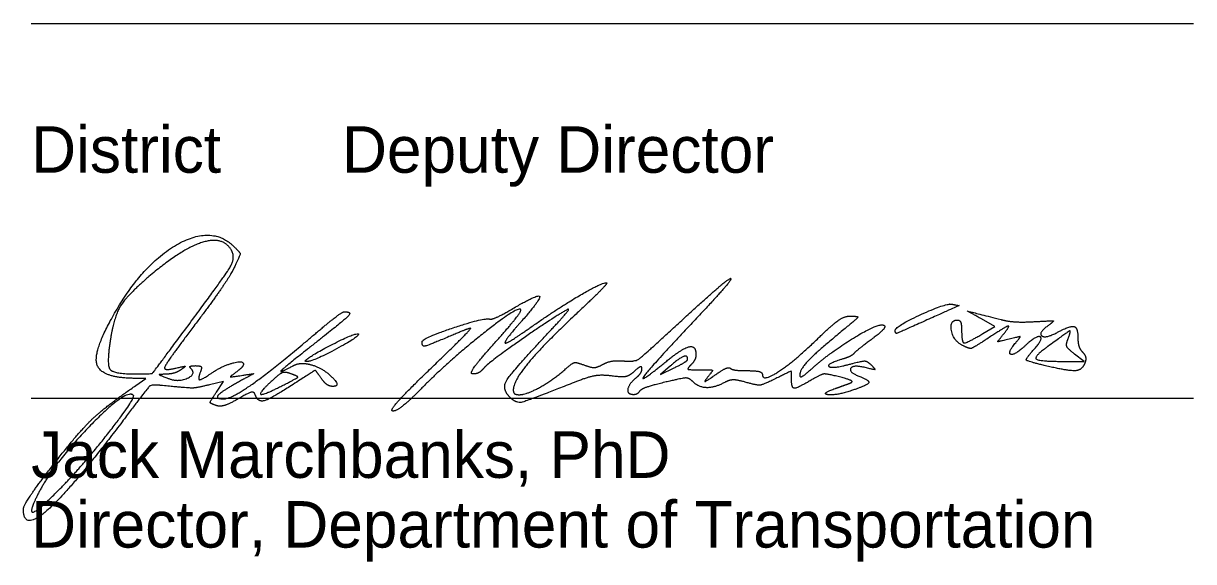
# Model space of a CAD drawing. Extents: x 0 to 81.5, y 0 to 35.2.
# Drawn here: x 77.956 to 81.479, y 33.533 to 35.155 of the extents above; entities that cross this region are included whole.
import ezdxf

# ---------------------------------------------------------------- set-up
doc = ezdxf.new("R2010")
doc.units = 0
doc.layers.add('SH_Data', color=7, linetype='Continuous')
doc.layers.add('SH_Text', color=7, linetype='Continuous')

msp = doc.modelspace()

# ---------------------------------------------------------------- linework, layer by layer
at = {"layer": 'SH_Data'}
for p, q in [((77.9791, 35.1551), (81.4791, 35.1551)), ((77.9791, 34.0257), (81.4791, 34.0257))]:
    msp.add_line(p, q, dxfattribs=at)
at = {"layer": 'SH_Text'}
for p, q in [((78.4414, 34.2307), (78.4414, 34.2307)), ((80.5807, 34.2298), (80.5807, 34.2298)), ((79.9557, 34.1428), (79.9557, 34.1428)), ((78.8067, 34.1408), (78.8067, 34.1408)), ((79.1786, 34.1118), (79.1786, 34.1118)), ((81.0332, 34.1236), (81.0332, 34.1236)), ((78.7619, 34.0992), (78.7619, 34.0992))]:
    msp.add_line(p, q, dxfattribs=at)
for points in [[(80.8445, 34.2203), (80.8809, 34.2418), (80.8402, 34.2647)], [(81.0932, 34.1367), (81.1494, 34.1368), (81.1207, 34.1589)], [(79.904, 34.1232), (79.8744, 34.0975), (79.9151, 34.1172)], [(78.2938, 34.0637), (78.3244, 34.085), (78.2866, 34.0856)], [(78.5367, 34.0439), (78.5579, 34.0762), (78.5162, 34.0662)]]:
    msp.add_lwpolyline(points, dxfattribs=at)
for points in [[(78.2301, 34.2815), (78.3163, 34.4318), (78.5245, 34.5479), (78.5901, 34.4822)], [(78.5812, 34.473), (78.5552, 34.515), (78.4291, 34.4739), (78.3338, 34.3922)], [(78.4414, 34.2307), (78.5628, 34.3941), (78.5952, 34.4503), (78.5812, 34.473)], [(78.5901, 34.4822), (78.6089, 34.4634), (78.6089, 34.4584), (78.5906, 34.42)], [(78.3338, 34.3922), (78.2671, 34.3352), (78.2283, 34.2711), (78.2172, 34.1998)], [(78.5906, 34.42), (78.5797, 34.397), (78.5279, 34.3214), (78.4757, 34.252)], [(79.4838, 34.2399), (79.5644, 34.2965), (79.6957, 34.3738), (79.7114, 34.3738)], [(79.7114, 34.3738), (79.7163, 34.3738), (79.675, 34.3312), (79.6196, 34.2791)], [(79.9381, 34.2603), (80.0131, 34.3294), (80.0791, 34.386), (80.0849, 34.3861)], [(80.0849, 34.3861), (80.0906, 34.3862), (80.0386, 34.326), (79.9692, 34.2524)], [(79.4249, 34.2934), (79.5036, 34.3396), (79.5159, 34.3263), (79.4566, 34.259)], [(78.8202, 34.208), (78.8707, 34.2508), (78.9162, 34.286), (78.9213, 34.2861)], [(78.9213, 34.2861), (78.9462, 34.2866), (78.9228, 34.261), (78.8369, 34.1938)], [(79.4529, 34.2932), (79.4433, 34.3028), (79.2336, 34.1359), (79.1557, 34.0566)], [(79.5932, 34.2927), (79.5442, 34.265), (79.3558, 34.1327), (79.3426, 34.1168)], [(79.3592, 34.2642), (79.3648, 34.2624), (79.3943, 34.2755), (79.4249, 34.2934)], [(79.3751, 34.1928), (79.4214, 34.2445), (79.4564, 34.2897), (79.4529, 34.2932)], [(79.528, 34.2138), (79.5742, 34.2631), (79.6035, 34.2986), (79.5932, 34.2927)], [(80.5807, 34.2298), (80.5807, 34.2422), (80.7335, 34.3126), (80.7524, 34.3089)], [(80.7524, 34.3089), (80.7731, 34.3048), (80.7739, 34.3053), (80.6522, 34.2506)], [(80.8402, 34.2647), (80.7973, 34.2888), (80.7964, 34.2889), (80.8994, 34.2625)], [(78.2866, 34.0856), (78.1887, 34.0873), (78.1653, 34.1684), (78.2301, 34.2815)], [(78.4757, 34.252), (78.4234, 34.1827), (78.3807, 34.122), (78.3807, 34.1172)], [(79.1559, 34.1956), (79.1561, 34.2062), (79.3435, 34.2694), (79.3592, 34.2642)], [(79.4566, 34.259), (79.4286, 34.2272), (79.4057, 34.1975), (79.4057, 34.1931)], [(79.6196, 34.2791), (79.52, 34.1853), (79.4307, 34.0772), (79.4307, 34.0502)], [(79.7631, 34.138), (79.7966, 34.1351), (79.8201, 34.1516), (79.9381, 34.2603)], [(79.9692, 34.2524), (79.8397, 34.1149), (79.8076, 34.0676), (79.8898, 34.1354)], [(80.3463, 34.2041), (80.3915, 34.2479), (80.4287, 34.2736), (80.4463, 34.2732)], [(80.4463, 34.2732), (80.4706, 34.2727), (80.4668, 34.2664), (80.4182, 34.2263)], [(80.6522, 34.2506), (80.5897, 34.2225), (80.5807, 34.2199), (80.5807, 34.2298)], [(80.7817, 34.1857), (80.7552, 34.1999), (80.7442, 34.2613), (80.7682, 34.2613)], [(80.7682, 34.2613), (80.7751, 34.2613), (80.7807, 34.2472), (80.7807, 34.23)], [(80.8994, 34.2625), (80.9201, 34.2572), (80.9651, 34.2544), (80.9994, 34.2564)], [(80.9994, 34.2564), (81.0543, 34.2595), (81.0592, 34.2578), (81.0393, 34.243)], [(78.2953, 34.0988), (78.342, 34.0988), (78.3465, 34.1029), (78.4414, 34.2307)], [(78.8067, 34.1408), (78.8271, 34.1587), (78.9592, 34.2245), (78.9643, 34.2193)], [(78.9643, 34.2193), (78.9705, 34.2131), (78.8279, 34.1363), (78.8102, 34.1363)], [(79.1786, 34.1118), (79.2496, 34.1803), (79.3049, 34.2363), (79.3015, 34.2363)], [(79.3015, 34.2363), (79.2981, 34.2363), (79.269, 34.225), (79.2369, 34.2113)], [(79.4209, 34.0282), (79.3957, 34.0534), (79.4246, 34.1035), (79.528, 34.2138)], [(79.4057, 34.1931), (79.4057, 34.1886), (79.4409, 34.2097), (79.4838, 34.2399)], [(80.4182, 34.2263), (80.3442, 34.1654), (80.2932, 34.1119), (80.2932, 34.0951)], [(80.3276, 34.1129), (80.3812, 34.1617), (80.5281, 34.2517), (80.545, 34.2461)], [(80.545, 34.2461), (80.5534, 34.2433), (80.5382, 34.2246), (80.5111, 34.2043)], [(80.7807, 34.23), (80.7807, 34.1932), (80.795, 34.191), (80.8445, 34.2203)], [(80.9041, 34.2154), (80.9285, 34.245), (80.9127, 34.2413), (80.8564, 34.204)], [(80.9235, 34.2037), (80.8904, 34.1955), (80.8886, 34.1966), (80.9041, 34.2154)], [(81.0393, 34.243), (81.0105, 34.2216), (81.0334, 34.2052), (81.0671, 34.2232)], [(81.101, 34.2045), (81.1109, 34.2302), (81.1026, 34.2272), (81.04, 34.1816)], [(81.0671, 34.2232), (81.1073, 34.2447), (81.1307, 34.239), (81.1307, 34.2075)], [(78.2172, 34.1998), (78.2058, 34.1265), (78.2272, 34.0988), (78.2953, 34.0988)], [(78.5589, 34.0238), (78.5819, 34.0238), (78.708, 34.1126), (78.8202, 34.208)], [(78.8369, 34.1938), (78.7437, 34.1207), (78.7223, 34.0992), (78.7662, 34.1227)], [(79.2369, 34.2113), (79.1743, 34.1844), (79.1556, 34.1808), (79.1559, 34.1956)], [(79.3093, 34.0988), (79.299, 34.0988), (79.3279, 34.1401), (79.3751, 34.1928)], [(79.8898, 34.1354), (79.9382, 34.1753), (79.9807, 34.1856), (79.9807, 34.1575)], [(80.1807, 34.0973), (80.1807, 34.0744), (80.276, 34.1359), (80.3463, 34.2041)], [(80.5111, 34.2043), (80.4841, 34.1842), (80.4591, 34.1642), (80.4557, 34.1599)], [(80.8564, 34.204), (80.8164, 34.1775), (80.8031, 34.1743), (80.7817, 34.1857)], [(80.9436, 34.193), (80.9582, 34.2106), (80.9559, 34.2118), (80.9235, 34.2037)], [(80.9723, 34.1843), (80.9404, 34.1543), (80.9173, 34.1613), (80.9436, 34.193)], [(80.9975, 34.1716), (81.028, 34.2053), (81.0063, 34.2162), (80.9723, 34.1843)], [(81.04, 34.1816), (80.9973, 34.1505), (81.0138, 34.1366), (81.0932, 34.1367)], [(81.1207, 34.1589), (81.1003, 34.1746), (81.0946, 34.1879), (81.101, 34.2045)], [(81.1307, 34.2075), (81.1307, 34.1917), (81.1371, 34.1724), (81.1449, 34.1646)], [(79.9557, 34.1428), (79.9557, 34.1563), (79.9316, 34.1472), (79.904, 34.1232)], [(79.9151, 34.1172), (79.9374, 34.1281), (79.9557, 34.1396), (79.9557, 34.1428)], [(79.9807, 34.1575), (79.9807, 34.1486), (79.9739, 34.1345), (79.9657, 34.1263)], [(80.4213, 34.1434), (80.3718, 34.1279), (80.3913, 34.1142), (80.4431, 34.1281)], [(80.4557, 34.1599), (80.4523, 34.1556), (80.4368, 34.1482), (80.4213, 34.1434)], [(81.0332, 34.1236), (80.9785, 34.1366), (80.9727, 34.1443), (80.9975, 34.1716)], [(81.1449, 34.1646), (81.1526, 34.1568), (81.1556, 34.1416), (81.1515, 34.1309)], [(78.3807, 34.1172), (78.3807, 34.1125), (78.3962, 34.1122), (78.4151, 34.1165)], [(78.4307, 34.1118), (78.4204, 34.1049), (78.4007, 34.0987), (78.3869, 34.0982)], [(78.3911, 34.0855), (78.421, 34.0735), (78.4772, 34.0981), (78.4598, 34.1155)], [(78.4151, 34.1165), (78.4406, 34.1225), (78.4446, 34.1213), (78.4307, 34.1118)], [(78.4598, 34.1155), (78.4552, 34.1201), (78.4615, 34.1238), (78.4737, 34.1238)], [(78.4737, 34.1238), (78.4883, 34.1238), (78.4934, 34.1173), (78.4887, 34.105)], [(78.5248, 34.1032), (78.5537, 34.1229), (78.6182, 34.1405), (78.6182, 34.1285)], [(78.6182, 34.1285), (78.6182, 34.124), (78.6085, 34.1132), (78.5966, 34.1045)], [(78.7662, 34.1227), (78.7788, 34.1295), (78.8027, 34.1315), (78.8193, 34.1273)], [(78.8523, 34.0859), (78.8355, 34.11), (78.8334, 34.1096), (78.7677, 34.0672)], [(78.8102, 34.1363), (78.8054, 34.1363), (78.8039, 34.1383), (78.8067, 34.1408)], [(78.8193, 34.1273), (78.8554, 34.1182), (78.9138, 34.0613), (78.8871, 34.0613)], [(79.0682, 33.987), (79.0579, 33.9872), (79.1075, 34.0433), (79.1786, 34.1118)], [(79.3426, 34.1168), (79.3344, 34.1069), (79.3194, 34.0988), (79.3093, 34.0988)], [(79.4487, 34.0363), (79.4705, 34.0363), (79.5518, 34.0815), (79.5882, 34.1138)], [(79.5882, 34.1138), (79.6085, 34.1318), (79.6214, 34.1344), (79.6451, 34.1254)], [(79.6451, 34.1254), (79.6653, 34.1178), (79.6841, 34.1185), (79.7001, 34.1275)], [(79.7001, 34.1275), (79.7135, 34.135), (79.7418, 34.1397), (79.7631, 34.138)], [(79.7956, 34.1072), (79.78, 34.093), (79.7587, 34.0886), (79.7261, 34.0928)], [(79.8182, 34.1147), (79.8182, 34.1218), (79.808, 34.1185), (79.7956, 34.1072)], [(79.7994, 34.0863), (79.8098, 34.0948), (79.8182, 34.1076), (79.8182, 34.1147)], [(79.9657, 34.1263), (79.954, 34.1146), (79.9599, 34.1113), (79.9922, 34.1113)], [(79.9922, 34.1113), (80.0298, 34.1113), (80.0321, 34.1092), (80.0166, 34.0899)], [(80.0384, 34.0958), (80.0598, 34.1108), (80.0805, 34.1198), (80.0844, 34.1159)], [(80.0844, 34.1159), (80.0883, 34.112), (80.1116, 34.1088), (80.1361, 34.1088)], [(80.1361, 34.1088), (80.1606, 34.1088), (80.1807, 34.1036), (80.1807, 34.0973)], [(80.2682, 34.0847), (80.2682, 34.1076), (80.2671, 34.1076), (80.221, 34.0848)], [(80.2932, 34.0951), (80.2932, 34.0877), (80.3087, 34.0957), (80.3276, 34.1129)], [(80.4431, 34.1281), (80.4815, 34.1383), (80.4967, 34.1377), (80.5088, 34.1255)], [(80.4901, 34.118), (80.4533, 34.1271), (80.4401, 34.104), (80.4744, 34.0908)], [(80.5088, 34.1255), (80.5214, 34.1126), (80.5179, 34.1111), (80.4901, 34.118)], [(81.1515, 34.1309), (81.1434, 34.1098), (81.1022, 34.1072), (81.0332, 34.1236)], [(78.3869, 34.0982), (78.3645, 34.0973), (78.365, 34.096), (78.3911, 34.0855)], [(78.4887, 34.105), (78.4797, 34.0818), (78.4926, 34.0811), (78.5248, 34.1032)], [(78.6034, 34.0745), (78.5523, 34.0462), (78.5326, 34.0238), (78.5589, 34.0238)], [(78.5966, 34.1045), (78.5777, 34.0906), (78.5796, 34.0893), (78.6122, 34.0943)], [(78.6122, 34.0943), (78.649, 34.0998), (78.6489, 34.0996), (78.6034, 34.0745)], [(78.7088, 34.0826), (78.6646, 34.0422), (78.6758, 34.0333), (78.7338, 34.0629)], [(78.7619, 34.0992), (78.7447, 34.1055), (78.7282, 34.1004), (78.7088, 34.0826)], [(78.7338, 34.0629), (78.7802, 34.0865), (78.7838, 34.0912), (78.7619, 34.0992)], [(78.8871, 34.0613), (78.8775, 34.0613), (78.8618, 34.0724), (78.8523, 34.0859)], [(79.6206, 34.0757), (79.4745, 34.018), (79.4395, 34.0096), (79.4209, 34.0282)], [(79.7261, 34.0928), (79.6969, 34.0965), (79.6571, 34.0901), (79.6206, 34.0757)], [(79.7925, 34.0363), (79.7741, 34.0363), (79.7787, 34.069), (79.7994, 34.0863)], [(79.8868, 34.0737), (79.8484, 34.0645), (79.8141, 34.0523), (79.8106, 34.0466)], [(79.9711, 34.0759), (79.96, 34.087), (79.9399, 34.0865), (79.8868, 34.0737)], [(80.0674, 34.0734), (80.0367, 34.0569), (79.9888, 34.0581), (79.9711, 34.0759)], [(80.0166, 34.0899), (80.0046, 34.0749), (80.0111, 34.0766), (80.0384, 34.0958)], [(80.1319, 34.0734), (80.105, 34.0811), (80.0819, 34.0811), (80.0674, 34.0734)], [(80.221, 34.0848), (80.1836, 34.0663), (80.165, 34.0639), (80.1319, 34.0734)], [(80.3301, 34.0817), (80.2851, 34.0551), (80.2682, 34.0559), (80.2682, 34.0847)], [(80.4133, 34.0897), (80.3745, 34.0996), (80.3577, 34.098), (80.3301, 34.0817)], [(80.4432, 34.0705), (80.4546, 34.0746), (80.4429, 34.0822), (80.4133, 34.0897)], [(80.4744, 34.0908), (80.505, 34.0791), (80.4961, 34.0642), (80.4493, 34.0487)], [(78.2866, 34.0345), (78.2657, 34.0554), (78.0472, 33.8297), (78.0009, 33.7394)], [(78.0428, 33.8216), (78.1205, 33.922), (78.2006, 33.9993), (78.2938, 34.0637)], [(78.375, 34.0638), (78.3416, 34.0672), (78.3298, 34.0567), (78.2532, 33.955)], [(78.5162, 34.0662), (78.4758, 34.0564), (78.4535, 34.056), (78.375, 34.0638)], [(78.5355, 34.0039), (78.5173, 34.0108), (78.5174, 34.0145), (78.5367, 34.0439)], [(78.6532, 34.0375), (78.6504, 34.046), (78.6311, 34.0408), (78.6021, 34.0237)], [(78.7677, 34.0672), (78.6988, 34.0228), (78.6613, 34.0131), (78.6532, 34.0375)], [(79.1557, 34.0566), (79.1179, 34.0181), (79.0785, 33.9868), (79.0682, 33.987)], [(79.4307, 34.0502), (79.4307, 34.0425), (79.4388, 34.0363), (79.4487, 34.0363)], [(79.8106, 34.0466), (79.8071, 34.0409), (79.7989, 34.0363), (79.7925, 34.0363)], [(80.4493, 34.0487), (80.4027, 34.0334), (80.3554, 34.0391), (80.3994, 34.0548)], [(80.3994, 34.0548), (80.4132, 34.0597), (80.4329, 34.0667), (80.4432, 34.0705)], [(78.071, 33.7581), (78.1386, 33.8272), (78.2943, 34.0268), (78.2866, 34.0345)], [(78.6021, 34.0237), (78.5764, 34.0085), (78.5465, 33.9996), (78.5355, 34.0039)], [(78.2532, 33.955), (78.1008, 33.7529), (77.9557, 33.6243), (77.9557, 33.6913)], [(77.9557, 33.6913), (77.9557, 33.7009), (77.9949, 33.7596), (78.0428, 33.8216)], [(78.0009, 33.7394), (77.9696, 33.6784), (78.0013, 33.6869), (78.071, 33.7581)]]:
    msp.add_open_spline(points, degree=2, dxfattribs=at)

# ---------------------------------------------------------------- texts
for s, p in [('District       Deputy Director', (77.9791, 34.7051)), ('Jack Marchbanks, PhD', (77.9791, 33.7857)), ('Director, Department of Transportation', (77.9791, 33.5757))]:
    msp.add_text(s, height=0.14, dxfattribs=at).set_placement(p)

doc.saveas('drawing.dxf')
